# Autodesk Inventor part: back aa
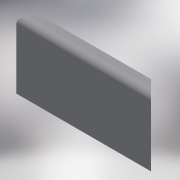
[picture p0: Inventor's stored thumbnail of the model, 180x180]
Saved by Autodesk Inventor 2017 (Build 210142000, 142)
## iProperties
Created: 2017-11
Part Number: back aa
Material: Generic
Document SubType Name: Modeling
Designer: lshopper
Density: 1 g/cm^3
Appearance: Default
Author: lshopper
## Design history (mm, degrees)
sketch "Sketch1"
  geometry: L1 (101.6, 16.803)-(-101.6, 16.803); L2 (-101.6, 16.803)-(-82.55, -2.247); L3 (-82.55, -2.247)-(82.55, -2.247); L4 (82.55, -2.247)-(101.6, 16.803); 2 further points
  constraints: 8 end point, 1 horizontal, 1 midpoint, 1 parallel, 1 vertical alignment
  dimensions: "d0" = 19.05 distance between parallel lines of L3 L1; "d1" = 203.2 distance of L1.start L1.end; "d2" = 45 deg angle of L1 L4; "d3" = 45 deg angle of L1 L2
extrude "Extrusion1" new body sketch "Sketch1" distance "d4" = 101.6; taper "d5" = 0 deg
fillet "Fillet1" dims "d8" = 9.525
body "Solid1"
